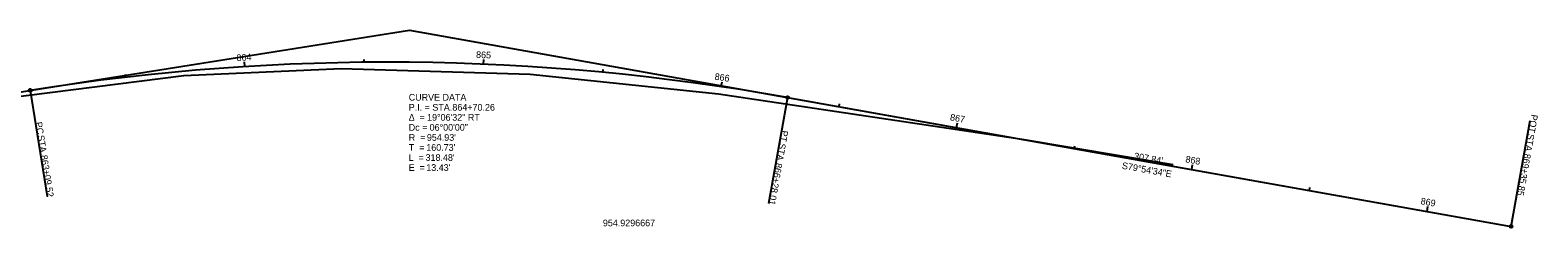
# Model space of a CAD drawing. Extents: x 115987 to 120394, y 324408 to 325987.
# Drawn here: x 117852 to 118483, y 325486 to 325569 of the extents above; entities that cross this region are included whole.
import ezdxf

# ---------------------------------------------------------------- set-up
doc = ezdxf.new("R2010")
doc.units = 0
for name, color, linetype in [('_CIVIL_CONSTRUCTION', 7, 'Continuous'), ('DT_X_Break_Line', 7, 'Continuous'), ('DT_X_Contour_Major', 7, 'Continuous'), ('DT_X_Island', 7, 'Continuous'), ('DT_X_Terrain_Boundary', 7, 'Continuous'), ('DT_X_Void', 7, 'Continuous'), ('SV_Control_Point', 7, 'Continuous')]:
    doc.layers.add(name, color=color, linetype=linetype)

msp = doc.modelspace()

# ---------------------------------------------------------------- linework, layer by layer
at = {"layer": '_CIVIL_CONSTRUCTION'}
msp.add_lwpolyline([(117546.25, 325495.29), (117570.94, 325499.21), (117766.5, 325531.11), (117916.3, 325550), (117982.12, 325552.99), (118061.23, 325550.63), (118140.16, 325542.3), (118267.24, 325523.46), (118330.42, 325512.77)], dxfattribs=at)
at = {"layer": 'DT_X_Contour_Major'}
for p, q in [((117570.94, 325499.21), (118010.69, 325569)), ((118010.69, 325569), (118472.02, 325486.91)), ((118168.94, 325540.84), (118472.02, 325486.91)), ((118168.94, 325540.84), (118472.02, 325486.91))]:
    msp.add_line(p, q, dxfattribs=at)
msp.add_arc((118001.63, 324600.68), 954.93, 79.90946, 99.01845, dxfattribs=at)
msp.add_arc((118001.63, 324600.68), 954.93, 79.90946, 99.01845, dxfattribs=at)
msp.add_arc((118001.63, 324600.68), 954.93, 79.90946, 99.01845, dxfattribs=at)
at = {"layer": 'DT_X_Terrain_Boundary'}
for p, q in [((117941.84, 325553.74), (117941.71, 325555.73)), ((117991.8, 325555.56), (117991.79, 325556.76)), ((118041.79, 325554.77), (118041.87, 325556.76)), ((117892.04, 325549.3), (117891.9, 325550.49)), ((118091.67, 325551.36), (118091.78, 325552.55)), ((118141.3, 325545.34), (118141.59, 325547.32)), ((118190.59, 325536.99), (118190.8, 325538.17)), ((118239.82, 325528.23), (118240.17, 325530.2)), ((118289.05, 325519.47), (118289.26, 325520.65)), ((118338.27, 325510.71), (118338.62, 325512.68)), ((118387.5, 325501.95), (118387.71, 325503.13)), ((118436.73, 325493.19), (118437.08, 325495.16))]:
    msp.add_line(p, q, dxfattribs=at)
at = {"layer": 'DT_X_Void'}
for p, q in [((117851.95, 325543.81), (117859, 325499.36)), ((118168.94, 325540.84), (118161.06, 325496.54)), ((118472.02, 325486.91), (118479.9, 325531.21))]:
    msp.add_line(p, q, dxfattribs=at)
for centre in [(117851.95, 325543.81), (118168.94, 325540.84), (118472.02, 325486.91)]:
    msp.add_circle(centre, 0.6, dxfattribs=at)

# ---------------------------------------------------------------- texts
at = {"layer": 'DT_X_Break_Line'}
msp.add_text('S79°54\'34"E', height=2.8, rotation=349.90946, dxfattribs=at).set_placement((118308.87, 325511.06))
at = {"layer": 'DT_X_Contour_Major'}
msp.add_text('954.9296667', height=2.8, dxfattribs=at).set_placement((118091.71, 325486.96))
at = {"layer": 'DT_X_Island'}
msp.add_text("307.84'", height=2.8, rotation=349.90946, dxfattribs=at).set_placement((118313.91, 325515.08))
at = {"layer": 'DT_X_Terrain_Boundary'}
for s, rotation, p in [('865', 357.58993, (118038.59, 325557.4)), ('864', 3.58993, (117938.42, 325556.03)), ('866', 351.58993, (118138.34, 325548.31)), ('867', 349.90946, (118236.89, 325531.29)), ('868', 349.90946, (118335.43, 325513.75)), ('869', 349.90946, (118433.9, 325496.23))]:
    msp.add_text(s, height=2.8, rotation=rotation, dxfattribs=at).set_placement(p)
at = {"layer": 'DT_X_Void'}
for s, rotation, p in [('PC', 279.01845, (117854.11, 325530.4)), ('POT', 259.90946, (118480.43, 325533.92)), (' STA. ', 279.01845, (117854.83, 325525.88)), ('PT', 259.90946, (118166.57, 325527.26)), (' STA. ', 259.90946, (118479.17, 325526.83)), ('863+09.52', 279.01845, (117856.32, 325516.54)), (' STA. ', 259.90946, (118165.79, 325522.91)), ('869+35.85', 259.90946, (118477.51, 325517.52)), ('866+28.01', 259.90946, (118164.14, 325513.6))]:
    msp.add_text(s, height=2.8, rotation=rotation, dxfattribs=at).set_placement(p)
at = {"layer": 'SV_Control_Point'}
for s, p in [('CURVE DATA', (118010.44, 325539.52)), ('P.I. = STA. ', (118010.44, 325535.32)), ('864+70.26', (118028.71, 325535.32)), ('Δ  = ', (118010.44, 325531.12)), ('Dc = ', (118010.44, 325526.92)), ('19°06\'32" RT', (118018.12, 325531.12)), ('06°00\'00"', (118019.18, 325526.92)), ('R  = ', (118010.44, 325522.72)), ("954.93'", (118018.03, 325522.72)), ('T  = ', (118010.44, 325518.52)), ('L  = ', (118010.44, 325514.32)), ("318.48'", (118017.48, 325514.32)), ("160.73'", (118017.78, 325518.52)), ('E  = ', (118010.44, 325510.12)), ("13.43'", (118017.78, 325510.12))]:
    msp.add_text(s, height=2.8, dxfattribs=at).set_placement(p)

doc.saveas('drawing.dxf')
